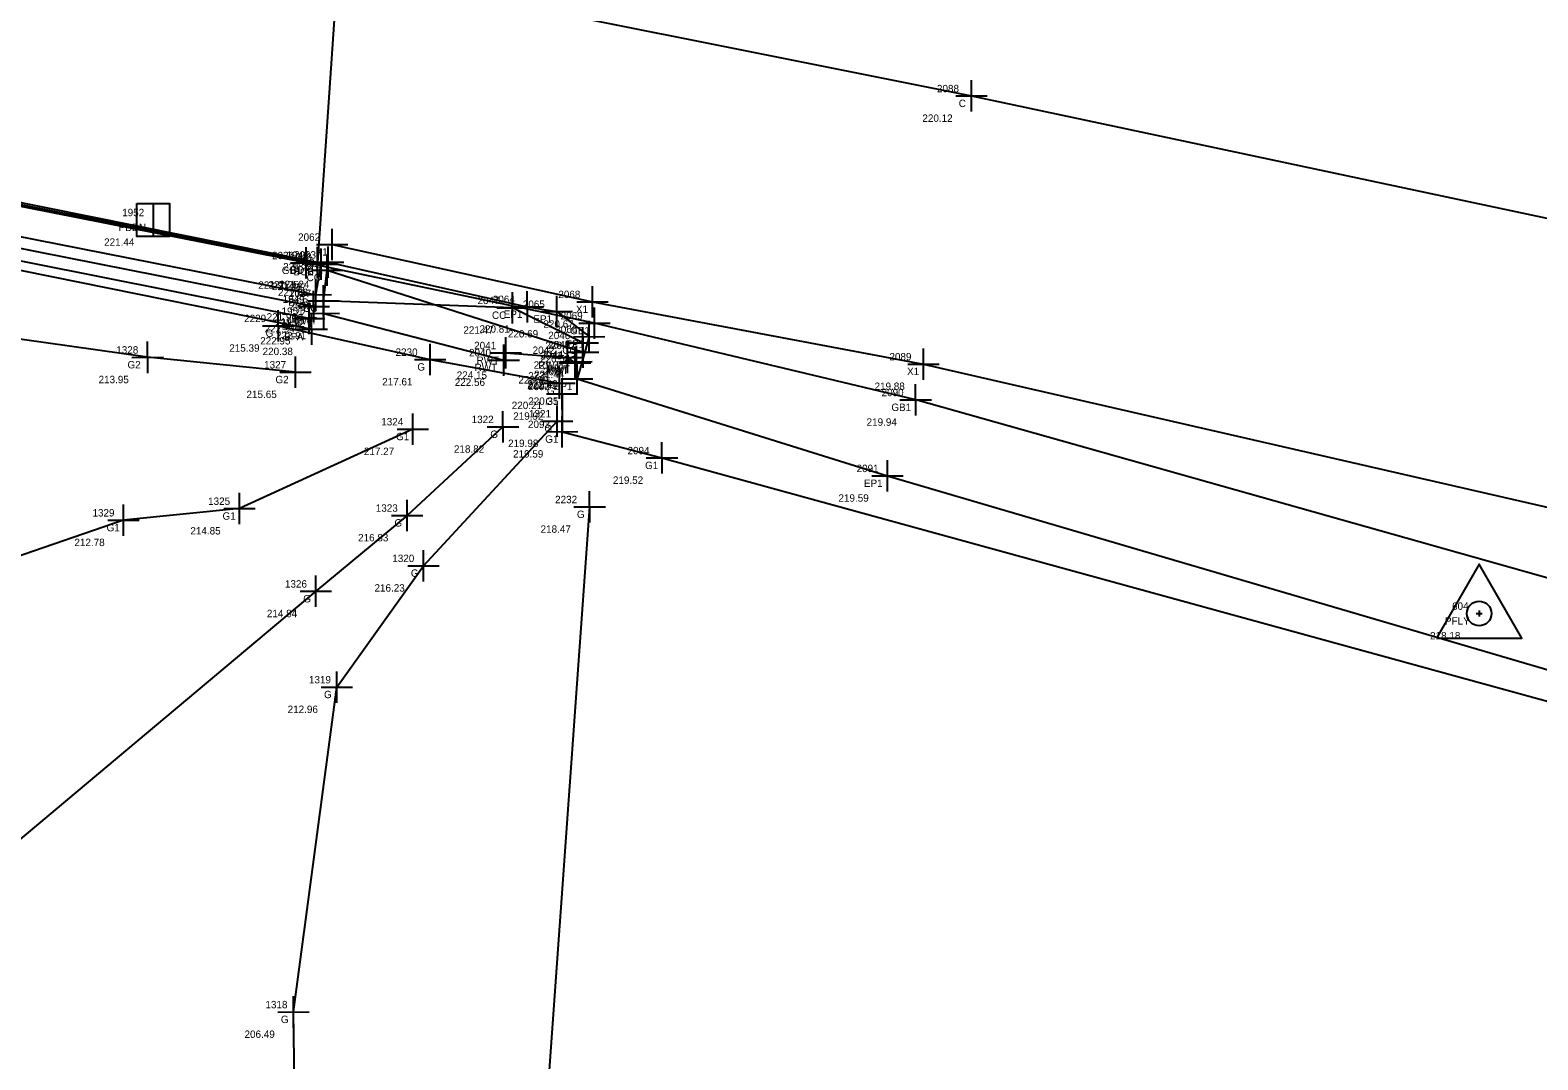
# Model space of a CAD drawing. Extents: x 1158983 to 1160032, y 610902 to 611573.
# Drawn here: x 1159660.7 to 1159721.8, y 611163.9 to 611205.7 of the extents above; entities that cross this region are included whole.
import ezdxf

# ---------------------------------------------------------------- set-up
doc = ezdxf.new("R2010")
doc.units = 0
for name, color, linetype in [('Default', 7, 'Continuous'), ('S_Bridge_Curb', 7, 'Continuous'), ('S_Bridge_Deck', 7, 'Continuous'), ('S_Bridge_Downspout', 7, 'Continuous'), ('S_Bridge_Fascia', 7, 'Continuous'), ('S_Control_Temp_Traverse', 7, 'Continuous'), ('S_Curb_Type_2', 7, 'Continuous'), ('S_Field_Code', 7, 'Continuous'), ('S_Ground_Elevation', 7, 'Continuous'), ('S_Guardrail_Beam', 7, 'Continuous'), ('S_Misc_MiscFeature', 7, 'Continuous'), ('S_Point_Elevation', 7, 'Continuous'), ('S_Point_Name', 7, 'Continuous'), ('S_RetWall_Top', 7, 'Continuous'), ('S_Roadway_Centerline', 7, 'Continuous'), ('S_Roadway_Edge_Pavement', 7, 'Continuous'), ('S_Roadway_Edge_TW', 7, 'Continuous'), ('S_Survey_Shot', 7, 'Continuous')]:
    doc.layers.add(name, color=color, linetype=linetype)

msp = doc.modelspace()

# ---------------------------------------------------------------- linework, layer by layer
at = {"layer": 'Default'}
msp.add_line((1159665.676, 611198.009), (1159665.676, 611198.009), dxfattribs=at)
at = {"layer": 'S_Bridge_Curb'}
msp.add_lwpolyline([(1159672.265, 611194.975), (1159672.481, 611196.211), (1159629.974, 611204.626), (1159629.621, 611203.384)], close=True, dxfattribs=at)
at = {"layer": 'S_Bridge_Deck'}
msp.add_lwpolyline([(1159333.801, 611289.348), (1159375.965, 611280.699), (1159433.546, 611269.247), (1159503.551, 611254.972), (1159573.652, 611240.691), (1159630.945, 611229.008), (1159674.004, 611220.503), (1159672.341, 611196.28), (1159630.068, 611204.797), (1159572.75, 611216.514), (1159502.493, 611230.859), (1159432.439, 611245.062), (1159375.072, 611256.503), (1159331.888, 611265.329)], close=True, dxfattribs=at)
at = {"layer": 'S_Bridge_Downspout'}
msp.add_line((1159665.676, 611198.676), (1159665.676, 611197.342), dxfattribs=at)
msp.add_lwpolyline([(1159665.009, 611198.676), (1159666.342, 611198.676), (1159666.342, 611197.342), (1159665.009, 611197.342)], close=True, dxfattribs=at)
at = {"layer": 'S_Bridge_Fascia'}
msp.add_lwpolyline([(1159672.101, 611193.576), (1159672.004, 611194.007), (1159629.69, 611202.438), (1159629.678, 611202.167)], close=True, dxfattribs=at)
at = {"layer": 'S_Control_Temp_Traverse'}
for p, q in [((1159719.301, 611182.047), (1159719.551, 611182.047)), ((1159719.426, 611182.171), (1159719.426, 611181.922))]:
    msp.add_line(p, q, dxfattribs=at)
msp.add_lwpolyline([(1159717.697, 611181.049), (1159721.155, 611181.049), (1159719.426, 611184.043)], close=True, dxfattribs=at)
msp.add_circle((1159719.426, 611182.047), 0.499, dxfattribs=at)
at = {"layer": 'S_Curb_Type_2'}
msp.add_lwpolyline([(1159672.585, 611194.727), (1159672.725, 611195.973), (1159683.103, 611192.647), (1159683.089, 611193.024), (1159680.238, 611194.444)], close=True, dxfattribs=at)
at = {"layer": 'S_Ground_Elevation'}
for points in [[(1159671.448, 611191.835), (1159665.451, 611192.436), (1159654.219, 611194.018), (1159640.99, 611197.041)], [(1159670.75, 611193.713), (1159676.9, 611192.346), (1159682.151, 611191.387)], [(1159682.259, 611190.954), (1159682.253, 611189.42), (1159686.301, 611188.354), (1159724.794, 611177.777), (1159771.526, 611168.443), (1159822.994, 611157.758), (1159878.115, 611146.533), (1159922.279, 611137.201), (1159937.967, 611131.955), (1159952.302, 611126.768), (1159965.774, 611121.294)], [(1159673.98, 611148.194), (1159671.561, 611151.308), (1159671.368, 611165.887), (1159673.116, 611179.063), (1159676.637, 611183.984), (1159682.051, 611189.85)], [(1159676.206, 611189.524), (1159669.173, 611186.301), (1159664.473, 611185.83), (1159655.602, 611182.774), (1159645.003, 611179.475)], [(1159679.856, 611189.617), (1159675.97, 611186.023), (1159672.274, 611182.947), (1159659.776, 611172.465), (1159653.662, 611164.642)], [(1159683.369, 611186.37), (1159680.513, 611146.541), (1159706.784, 611139.403), (1159766.662, 611134.29), (1159820.912, 611129.757), (1159888.671, 611122.169), (1159937.459, 611114.958), (1159962.2, 611115.558), (1159959.265, 611100.796), (1159986.294, 611096.455)]]:
    msp.add_lwpolyline(points, dxfattribs=at)
at = {"layer": 'S_Guardrail_Beam'}
msp.add_lwpolyline([(1159962.355, 611128.723), (1159954.927, 611131.331), (1159940.804, 611136.335), (1159922.846, 611140.981), (1159878.137, 611150.269), (1159824.181, 611161.329), (1159771.192, 611171.967), (1159724.558, 611182.82), (1159696.585, 611190.71), (1159683.564, 611193.82), (1159671.877, 611196.264), (1159629.625, 611204.61), (1159571.633, 611216.492), (1159501.577, 611230.682), (1159431.638, 611244.705), (1159374.182, 611256.374), (1159332.105, 611265.121)], dxfattribs=at)
at = {"layer": 'S_Misc_MiscFeature'}
msp.add_lwpolyline([(1159672.181, 611194.494), (1159629.815, 611202.879)], dxfattribs=at)
at = {"layer": 'S_RetWall_Top'}
msp.add_lwpolyline([(1159672.592, 611194.218), (1159679.89, 611192.326), (1159679.97, 611192.615), (1159682.471, 611192.424), (1159682.781, 611192.204), (1159682.835, 611192.259)], dxfattribs=at)
at = {"layer": 'S_Roadway_Centerline'}
msp.add_lwpolyline([(1159673.769, 611208.069), (1159698.846, 611203.034), (1159728.395, 611196.752), (1159772.97, 611187.891), (1159828.817, 611176.689), (1159879.967, 611166.333), (1159926.666, 611157.012), (1159971.696, 611147.916), (1160001.646, 611141.493), (1160028.762, 611136.127)], dxfattribs=at)
at = {"layer": 'S_Roadway_Edge_Pavement'}
msp.add_lwpolyline([(1159672.769, 611196.291), (1159680.842, 611194.486), (1159682.044, 611194.29), (1159683.348, 611193.274), (1159682.867, 611191.559), (1159695.444, 611187.631), (1159724.424, 611179.109), (1159771.93, 611169.621), (1159823.571, 611159.104), (1159877.204, 611148.238), (1159922.704, 611138.662), (1159939.414, 611133.312), (1159952.757, 611128.663), (1159956.012, 611127.733), (1159960.843, 611127.391), (1159966.487, 611126.732), (1159986.189, 611124.904), (1159994.495, 611124.925), (1160026.367, 611121.156)], dxfattribs=at)
at = {"layer": 'S_Roadway_Edge_TW'}
msp.add_lwpolyline([(1159672.935, 611197.011), (1159683.483, 611194.687), (1159696.906, 611192.163), (1159725.478, 611185.596), (1159771.844, 611176.591), (1159825.819, 611165.687), (1159878.823, 611155.251), (1159923.996, 611146.174), (1159970.362, 611137.218), (1159997.428, 611131.161), (1160026.697, 611125.613)], dxfattribs=at)
at = {"layer": 'S_Survey_Shot'}
for p, q in [((1159698.848, 611202.398), (1159698.845, 611203.67)), ((1159698.21, 611203.033), (1159699.483, 611203.036)), ((1159698.846, 611203.034), (1159698.846, 611203.034)), ((1159672.936, 611196.375), (1159672.934, 611197.647)), ((1159672.299, 611197.01), (1159673.571, 611197.012)), ((1159672.935, 611197.011), (1159672.935, 611197.011)), ((1159671.878, 611195.628), (1159671.876, 611196.901)), ((1159672.343, 611195.644), (1159672.34, 611196.917)), ((1159672.483, 611195.575), (1159672.48, 611196.848)), ((1159672.726, 611195.336), (1159672.723, 611196.609)), ((1159672.77, 611195.655), (1159672.768, 611196.928)), ((1159671.241, 611196.263), (1159672.513, 611196.266)), ((1159671.705, 611196.279), (1159672.977, 611196.282)), ((1159671.845, 611196.21), (1159673.117, 611196.213)), ((1159671.877, 611196.264), (1159671.877, 611196.264)), ((1159672.088, 611195.971), (1159673.361, 611195.974)), ((1159672.133, 611196.29), (1159673.405, 611196.293)), ((1159672.341, 611196.28), (1159672.341, 611196.28)), ((1159672.481, 611196.211), (1159672.481, 611196.211)), ((1159672.725, 611195.973), (1159672.725, 611195.973)), ((1159672.769, 611196.291), (1159672.769, 611196.291)), ((1159672.267, 611194.339), (1159672.264, 611195.612)), ((1159672.586, 611194.091), (1159672.583, 611195.363)), ((1159683.484, 611194.051), (1159683.482, 611195.323)), ((1159671.629, 611194.974), (1159672.902, 611194.977)), ((1159671.949, 611194.726), (1159673.221, 611194.728)), ((1159672.006, 611193.371), (1159672.003, 611194.643)), ((1159672.183, 611193.858), (1159672.18, 611195.13)), ((1159672.265, 611194.975), (1159672.265, 611194.975)), ((1159672.585, 611194.727), (1159672.585, 611194.727)), ((1159672.593, 611193.582), (1159672.591, 611194.854)), ((1159680.24, 611193.807), (1159680.237, 611195.08)), ((1159680.844, 611193.849), (1159680.841, 611195.122)), ((1159682.045, 611193.654), (1159682.043, 611194.926)), ((1159682.847, 611194.685), (1159684.119, 611194.688)), ((1159683.483, 611194.687), (1159683.483, 611194.687)), ((1159670.751, 611193.077), (1159670.748, 611194.349)), ((1159671.368, 611194.006), (1159672.64, 611194.008)), ((1159671.545, 611194.493), (1159672.818, 611194.495)), ((1159671.956, 611194.217), (1159673.228, 611194.22)), ((1159672.004, 611194.007), (1159672.004, 611194.007)), ((1159672.102, 611192.94), (1159672.099, 611194.212)), ((1159672.181, 611194.494), (1159672.181, 611194.494)), ((1159672.592, 611194.218), (1159672.592, 611194.218)), ((1159679.602, 611194.442), (1159680.875, 611194.445)), ((1159680.206, 611194.484), (1159681.479, 611194.487)), ((1159680.238, 611194.444), (1159680.238, 611194.444)), ((1159680.842, 611194.486), (1159680.842, 611194.486)), ((1159681.408, 611194.288), (1159682.68, 611194.291)), ((1159682.044, 611194.29), (1159682.044, 611194.29)), ((1159683.565, 611193.183), (1159683.562, 611194.456)), ((1159670.113, 611193.712), (1159671.386, 611193.715)), ((1159670.75, 611193.713), (1159670.75, 611193.713)), ((1159671.464, 611193.574), (1159672.737, 611193.577)), ((1159672.101, 611193.576), (1159672.101, 611193.576)), ((1159682.927, 611193.818), (1159684.2, 611193.821)), ((1159683.091, 611192.388), (1159683.088, 611193.661)), ((1159683.349, 611192.638), (1159683.346, 611193.91)), ((1159683.564, 611193.82), (1159683.564, 611193.82)), ((1159665.453, 611191.799), (1159665.45, 611193.072)), ((1159676.902, 611191.71), (1159676.899, 611192.983)), ((1159679.892, 611191.69), (1159679.889, 611192.962)), ((1159679.972, 611191.979), (1159679.969, 611193.251)), ((1159682.453, 611193.023), (1159683.726, 611193.026)), ((1159682.472, 611191.788), (1159682.469, 611193.061)), ((1159682.712, 611193.273), (1159683.984, 611193.275)), ((1159682.782, 611191.568), (1159682.78, 611192.841)), ((1159682.837, 611191.623), (1159682.834, 611192.896)), ((1159683.089, 611193.024), (1159683.089, 611193.024)), ((1159683.105, 611192.011), (1159683.102, 611193.283)), ((1159683.348, 611193.274), (1159683.348, 611193.274)), ((1159696.907, 611191.527), (1159696.904, 611192.799)), ((1159664.815, 611192.434), (1159666.088, 611192.437)), ((1159665.451, 611192.436), (1159665.451, 611192.436)), ((1159671.449, 611191.199), (1159671.446, 611192.472)), ((1159676.264, 611192.345), (1159677.537, 611192.348)), ((1159676.9, 611192.346), (1159676.9, 611192.346)), ((1159679.254, 611192.325), (1159680.526, 611192.327)), ((1159679.334, 611192.614), (1159680.607, 611192.616)), ((1159679.89, 611192.326), (1159679.89, 611192.326)), ((1159679.97, 611192.615), (1159679.97, 611192.615)), ((1159681.835, 611192.423), (1159683.107, 611192.426)), ((1159682.145, 611192.203), (1159683.417, 611192.206)), ((1159682.199, 611192.258), (1159683.472, 611192.261)), ((1159682.467, 611192.646), (1159683.74, 611192.649)), ((1159682.471, 611192.424), (1159682.471, 611192.424)), ((1159682.781, 611192.204), (1159682.781, 611192.204)), ((1159682.835, 611192.259), (1159682.835, 611192.259)), ((1159682.868, 611190.923), (1159682.865, 611192.195)), ((1159683.103, 611192.647), (1159683.103, 611192.647)), ((1159696.269, 611192.162), (1159697.542, 611192.164)), ((1159696.906, 611192.163), (1159696.906, 611192.163)), ((1159670.811, 611191.834), (1159672.084, 611191.837)), ((1159671.448, 611191.835), (1159671.448, 611191.835)), ((1159682.152, 611190.75), (1159682.15, 611192.023)), ((1159682.23, 611191.558), (1159683.503, 611191.56)), ((1159682.261, 611190.318), (1159682.258, 611191.59)), ((1159682.867, 611191.559), (1159682.867, 611191.559)), ((1159681.515, 611191.385), (1159682.787, 611191.388)), ((1159681.623, 611190.953), (1159682.896, 611190.955)), ((1159682.151, 611191.387), (1159682.151, 611191.387)), ((1159682.259, 611190.954), (1159682.259, 611190.954)), ((1159696.586, 611190.074), (1159696.584, 611191.346)), ((1159682.052, 611189.214), (1159682.049, 611190.487)), ((1159695.949, 611190.709), (1159697.221, 611190.711)), ((1159696.585, 611190.71), (1159696.585, 611190.71)), ((1159676.208, 611188.888), (1159676.205, 611190.16)), ((1159679.858, 611188.981), (1159679.855, 611190.253)), ((1159681.415, 611189.849), (1159682.687, 611189.852)), ((1159682.051, 611189.85), (1159682.051, 611189.85)), ((1159682.255, 611188.784), (1159682.252, 611190.056)), ((1159675.57, 611189.523), (1159676.843, 611189.525)), ((1159676.206, 611189.524), (1159676.206, 611189.524)), ((1159679.22, 611189.616), (1159680.493, 611189.618)), ((1159679.856, 611189.617), (1159679.856, 611189.617)), ((1159681.617, 611189.419), (1159682.89, 611189.421)), ((1159682.253, 611189.42), (1159682.253, 611189.42)), ((1159686.302, 611187.718), (1159686.3, 611188.99)), ((1159685.665, 611188.353), (1159686.937, 611188.356)), ((1159686.301, 611188.354), (1159686.301, 611188.354)), ((1159695.445, 611186.995), (1159695.442, 611188.268)), ((1159694.807, 611187.63), (1159696.08, 611187.633)), ((1159695.444, 611187.631), (1159695.444, 611187.631)), ((1159669.175, 611185.665), (1159669.172, 611186.937)), ((1159675.972, 611185.387), (1159675.969, 611186.659)), ((1159683.371, 611185.734), (1159683.368, 611187.007)), ((1159664.474, 611185.194), (1159664.472, 611186.467)), ((1159668.537, 611186.3), (1159669.81, 611186.303)), ((1159669.173, 611186.301), (1159669.173, 611186.301)), ((1159675.334, 611186.022), (1159676.607, 611186.025)), ((1159675.97, 611186.023), (1159675.97, 611186.023)), ((1159682.733, 611186.369), (1159684.006, 611186.372)), ((1159683.369, 611186.37), (1159683.369, 611186.37)), ((1159663.837, 611185.829), (1159665.109, 611185.832)), ((1159664.473, 611185.83), (1159664.473, 611185.83)), ((1159676.639, 611183.347), (1159676.636, 611184.62)), ((1159672.275, 611182.311), (1159672.273, 611183.583)), ((1159676.001, 611183.982), (1159677.274, 611183.985)), ((1159676.637, 611183.984), (1159676.637, 611183.984)), ((1159671.638, 611182.946), (1159672.91, 611182.949)), ((1159672.274, 611182.947), (1159672.274, 611182.947)), ((1159673.118, 611178.427), (1159673.115, 611179.7)), ((1159672.48, 611179.062), (1159673.753, 611179.065)), ((1159673.116, 611179.063), (1159673.116, 611179.063)), ((1159671.37, 611165.251), (1159671.367, 611166.523)), ((1159670.732, 611165.886), (1159672.004, 611165.888)), ((1159671.368, 611165.887), (1159671.368, 611165.887))]:
    msp.add_line(p, q, dxfattribs=at)

# ---------------------------------------------------------------- texts
at = {"layer": 'S_Field_Code'}
for s, p in [('C', (1159698.331, 611202.584)), ('PBDN', (1159664.275, 611197.559)), ('X1', (1159672.264, 611196.561)), ('GB1', (1159670.892, 611195.814)), ('BDK', (1159671.24, 611195.83)), ('BCB', (1159671.366, 611195.761)), ('EP1', (1159671.812, 611195.841)), ('CC', (1159671.895, 611195.523)), ('BCB', (1159671.15, 611194.525)), ('CC', (1159671.756, 611194.277)), ('ZZ', (1159671.381, 611194.044)), ('RWT', (1159671.406, 611193.768)), ('CC', (1159679.409, 611193.994)), ('EP1', (1159679.886, 611194.036)), ('EP1', (1159681.088, 611193.84)), ('X1', (1159682.812, 611194.237)), ('G', (1159670.235, 611193.263)), ('BFA', (1159670.887, 611193.557)), ('BFA', (1159670.984, 611193.126)), ('GB1', (1159682.579, 611193.37)), ('CC', (1159682.26, 611192.574)), ('EP1', (1159682.391, 611192.824)), ('G2', (1159664.636, 611191.986)), ('G', (1159676.385, 611191.896)), ('RWT', (1159678.704, 611191.876)), ('RWT', (1159678.785, 611192.165)), ('RWT', (1159681.285, 611191.974)), ('RWT', (1159681.65, 611191.809)), ('CC', (1159682.274, 611192.197)), ('G2', (1159670.633, 611191.385)), ('RWT', (1159681.595, 611191.754)), ('X1', (1159696.235, 611191.713)), ('G', (1159681.636, 611190.937)), ('EP1', (1159681.91, 611191.109)), ('G1', (1159681.575, 611190.504)), ('GB1', (1159695.6, 611190.26)), ('G', (1159681.536, 611189.4)), ('G1', (1159675.522, 611189.074)), ('G', (1159679.342, 611189.167)), ('G1', (1159681.568, 611188.97)), ('G1', (1159685.616, 611187.904)), ('EP1', (1159694.487, 611187.181)), ('G1', (1159668.488, 611185.851)), ('G', (1159682.854, 611185.92)), ('G1', (1159663.788, 611185.38)), ('G', (1159675.456, 611185.573)), ('G', (1159676.122, 611183.534)), ('G', (1159671.759, 611182.497)), ('PFLY', (1159718.04, 611181.597)), ('G', (1159672.601, 611178.613)), ('G', (1159670.853, 611165.437))]:
    msp.add_text(s, height=0.3, dxfattribs=at).set_placement(p)
at = {"layer": 'S_Point_Elevation'}
for s, p in [('220.12', (1159696.857, 611201.984)), ('221.44', (1159663.687, 611196.959)), ('221.22', (1159670.946, 611195.961)), ('221.91', (1159669.938, 611195.214)), ('221.25', (1159670.352, 611195.23)), ('221.89', (1159670.492, 611195.161)), ('221.86', (1159670.736, 611194.923)), ('221.24', (1159670.78, 611195.241)), ('221.96', (1159670.276, 611193.925)), ('221.92', (1159670.596, 611193.677)), ('220.67', (1159681.494, 611193.637)), ('222.94', (1159670.192, 611193.444)), ('222.91', (1159670.653, 611193.168)), ('221.47', (1159678.249, 611193.394)), ('220.81', (1159678.903, 611193.436)), ('220.69', (1159680.055, 611193.24)), ('215.39', (1159668.761, 611192.663)), ('222.95', (1159670.015, 611192.957)), ('220.38', (1159670.112, 611192.526)), ('220.57', (1159681.575, 611192.77)), ('221.38', (1159681.1, 611191.974)), ('220.54', (1159681.359, 611192.224)), ('213.95', (1159663.462, 611191.386)), ('217.61', (1159674.961, 611191.296)), ('222.56', (1159677.901, 611191.276)), ('224.15', (1159677.982, 611191.565)), ('223.99', (1159680.482, 611191.374)), ('222.40', (1159680.846, 611191.209)), ('221.44', (1159681.114, 611191.597)), ('215.65', (1159669.459, 611190.785)), ('222.41', (1159680.842, 611191.154)), ('219.88', (1159694.917, 611191.113)), ('220.21', (1159680.212, 611190.337)), ('220.35', (1159680.878, 611190.509)), ('219.92', (1159680.271, 611189.904)), ('219.94', (1159694.596, 611189.66)), ('219.98', (1159680.062, 611188.8)), ('217.27', (1159674.218, 611188.474)), ('218.82', (1159677.868, 611188.567)), ('219.59', (1159680.264, 611188.37)), ('219.52', (1159684.312, 611187.304)), ('219.59', (1159693.455, 611186.581)), ('214.85', (1159667.184, 611185.251)), ('218.47', (1159681.38, 611185.32)), ('212.78', (1159662.484, 611184.78)), ('216.83', (1159673.982, 611184.973)), ('216.23', (1159674.648, 611182.934)), ('214.84', (1159670.285, 611181.897)), ('218.18', (1159717.437, 611180.997)), ('212.96', (1159671.127, 611178.013)), ('206.49', (1159669.379, 611164.837))]:
    msp.add_text(s, height=0.3, dxfattribs=at).set_placement(p)
at = {"layer": 'S_Point_Name'}
for s, p in [('2088', (1159697.448, 611203.184)), ('1952', (1159664.419, 611198.159)), ('2062', (1159671.551, 611197.161)), ('2036', (1159670.493, 611196.414)), ('1946', (1159671.085, 611196.43)), ('1948', (1159671.211, 611196.361)), ('2038', (1159671.326, 611196.123)), ('2063', (1159671.385, 611196.441)), ('1947', (1159670.992, 611195.125)), ('2037', (1159671.184, 611194.877)), ('1949', (1159670.925, 611194.644)), ('2039', (1159671.208, 611194.368)), ('2047', (1159678.823, 611194.594)), ('2064', (1159679.444, 611194.636)), ('2065', (1159680.66, 611194.44)), ('2068', (1159682.099, 611194.837)), ('2229', (1159669.363, 611193.863)), ('1950', (1159670.847, 611193.726)), ('1951', (1159670.878, 611194.157)), ('2069', (1159682.194, 611193.97)), ('2046', (1159681.691, 611193.174)), ('2066', (1159681.978, 611193.424)), ('1328', (1159664.18, 611192.586)), ('2230', (1159675.502, 611192.496)), ('2040', (1159678.48, 611192.476)), ('2041', (1159678.688, 611192.765)), ('2042', (1159681.058, 611192.574)), ('2045', (1159681.691, 611192.797)), ('1327', (1159670.174, 611191.985)), ('2043', (1159681.368, 611192.354)), ('2044', (1159681.409, 611192.409)), ('2089', (1159695.521, 611192.313)), ('2231', (1159680.88, 611191.537)), ('2067', (1159681.48, 611191.709)), ('2092', (1159680.875, 611191.104)), ('2090', (1159695.203, 611190.86)), ('1321', (1159680.91, 611190)), ('1324', (1159674.922, 611189.674)), ('1322', (1159678.586, 611189.767)), ('2093', (1159680.869, 611189.57)), ('2094', (1159684.903, 611188.504)), ('2091', (1159694.189, 611187.781)), ('1325', (1159667.903, 611186.451)), ('2232', (1159681.969, 611186.52)), ('1329', (1159663.216, 611185.98)), ('1323', (1159674.7, 611186.173)), ('1320', (1159675.369, 611184.134)), ('1326', (1159671.017, 611183.097)), ('604', (1159718.328, 611182.197)), ('1319', (1159671.99, 611179.213)), ('1318', (1159670.227, 611166.037))]:
    msp.add_text(s, height=0.3, dxfattribs=at).set_placement(p)

doc.saveas('drawing.dxf')
